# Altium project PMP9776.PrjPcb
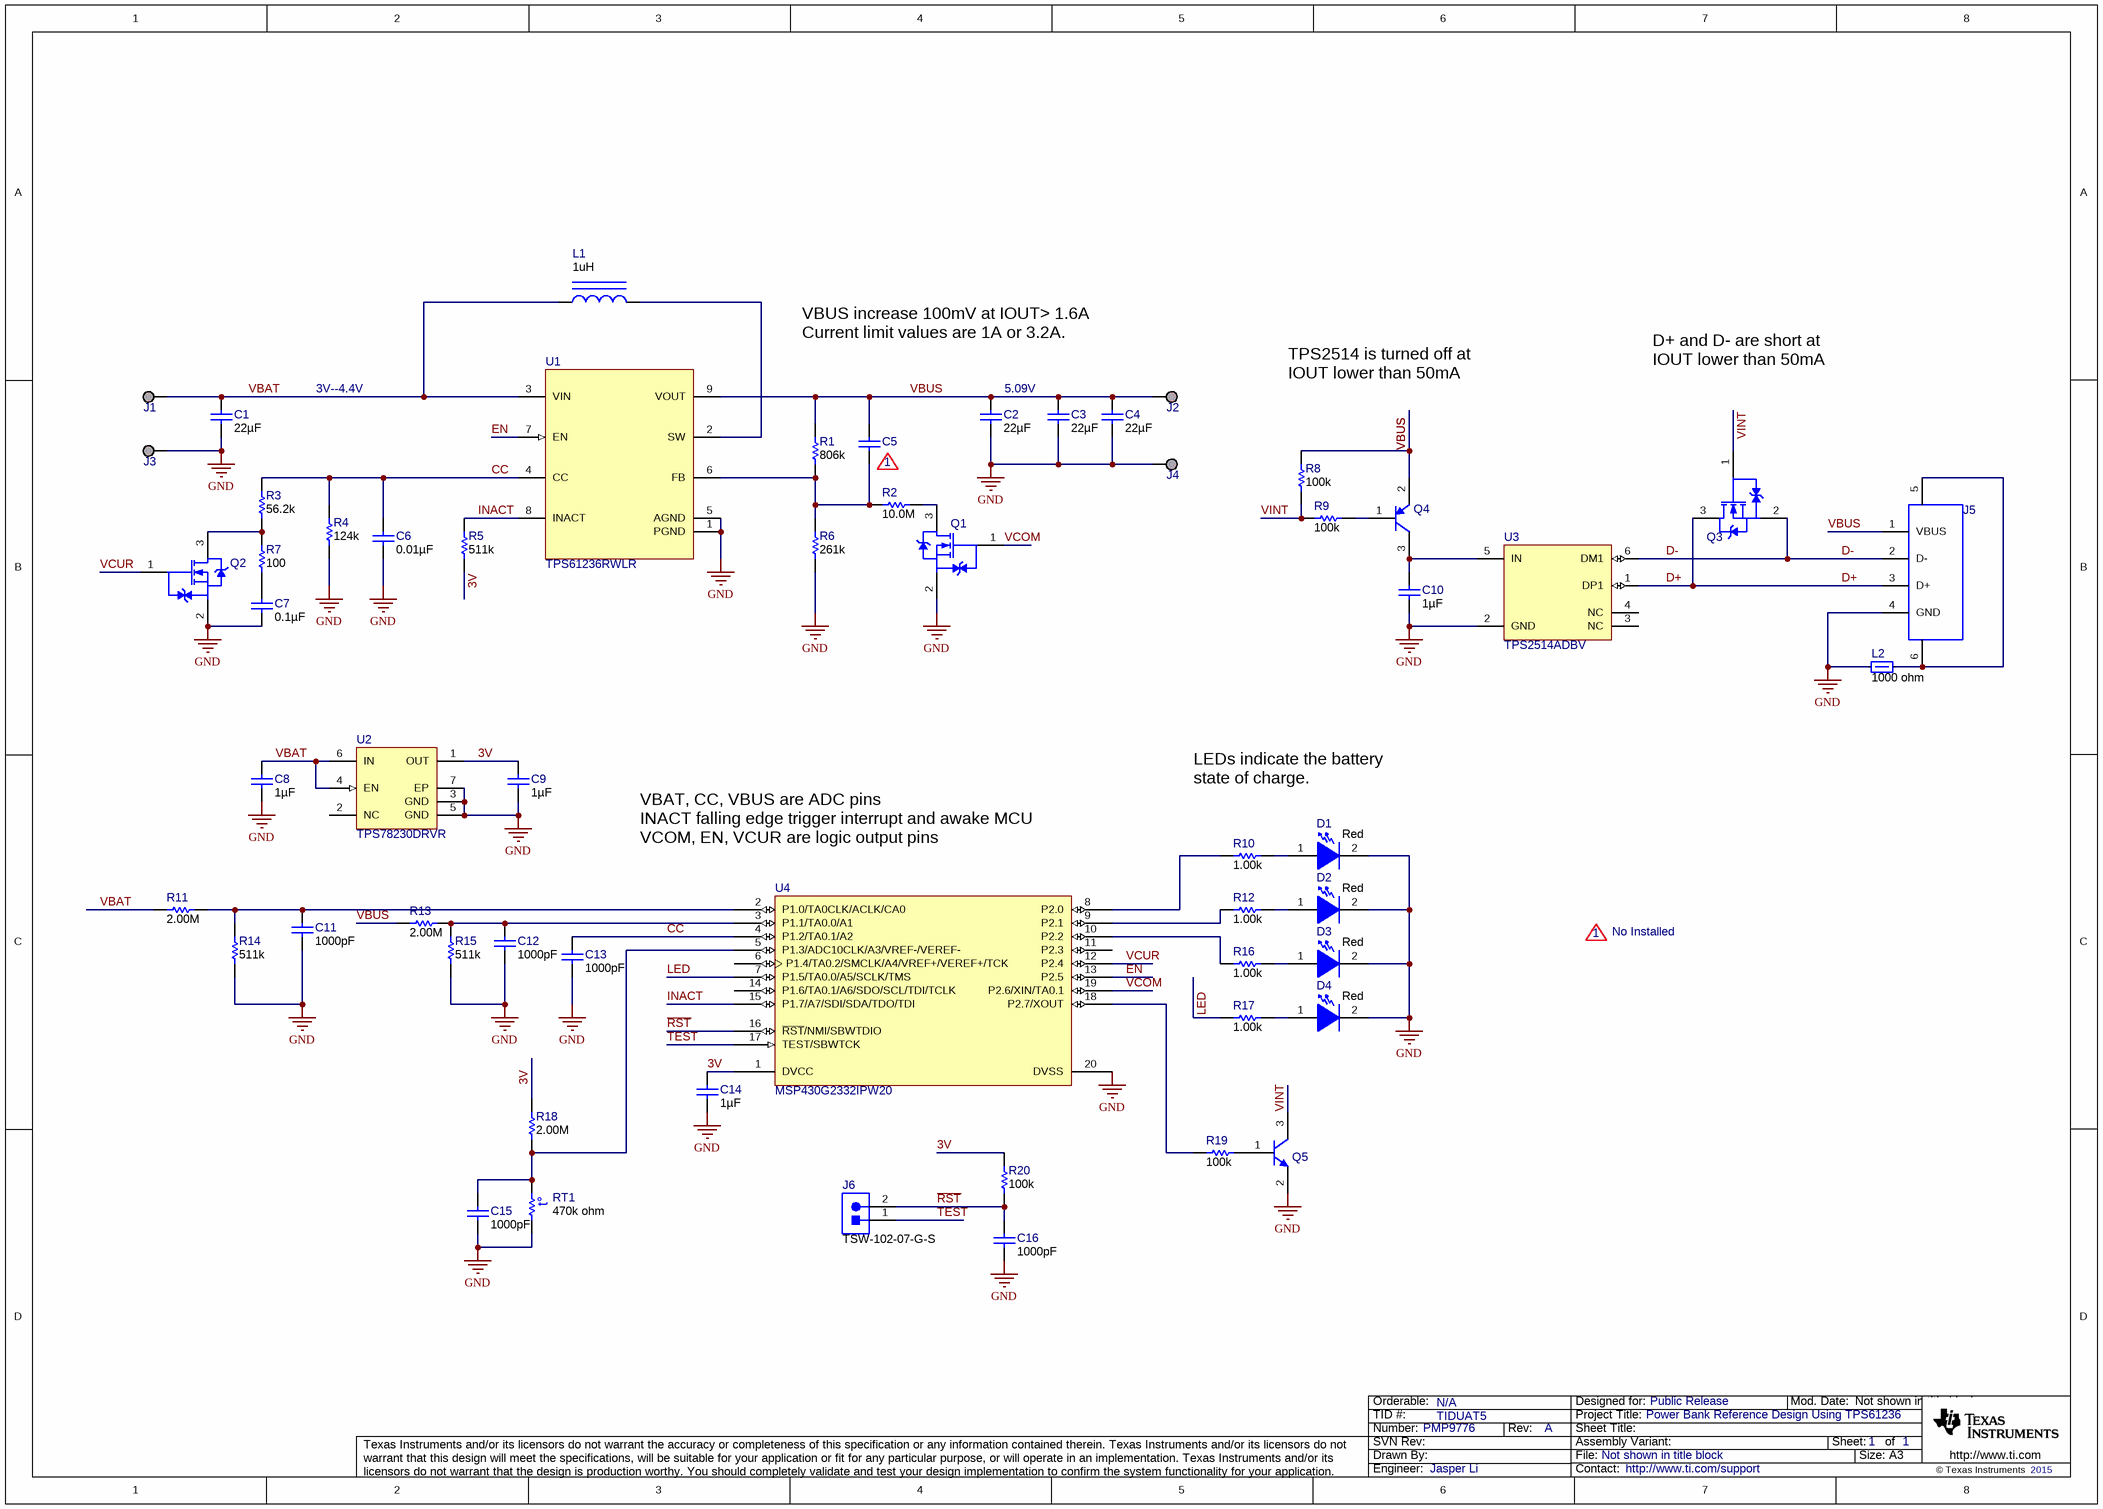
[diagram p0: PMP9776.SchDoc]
TID: TIDUAT5; TechSupport: http://www.ti.com/support; SCH_Rev: A; PRJ_Title: Power Bank Reference Design Using TPS61236; PRJ_Number: PMP9776; PRJ_Engineer: Jasper Li; PRJ_Customer: Public Release; PCB_Rev: A; PCB_Layout: Jasper Li; EVM_Orderable: N/A; CopyrightYear: 2015
2 sheets, 60 parts. Net scope: global (net labels, ports and power ports of the same name join across sheets).
Board file: PMP9776.PcbDoc
Sheets:
  PMP9776.SchDoc
  PMP9776_Hardware.SchDoc

## Sheet PMP9776.SchDoc
size A3; Date: Not shown in title block; ApprovedBy: Not shown in title block; CheckedBy: Not shown in title block; Author: Not shown in title block; CompanyName: Not shown in title block; Engineer: Not shown in title block; Organization: Not shown in title block; Address1: Not shown in title block; Address2: Not shown in title block; Address3: Not shown in title block; Address4: Not shown in title block; DocumentNumber: 1; Revision: Use project parameter SCH_Rev; SheetNumber: 1; SheetTotal: 1; PageSetup: Record=PageOptions¦CenterHorizontal=True¦CenterVertical=True¦PrintScale=0.70¦XCorrection=1.00¦YCorrection=1.00¦PrintKind=0¦BorderSize=5000000¦LeftOffset=0¦BottomOffset=0¦Orientation=2¦PaperLength=1000¦PaperWidth=1000¦Scale=100¦PaperSource=15¦PrintQuality=600¦MediaType=1¦DitherType=10¦PrintScaleMode=1¦PaperKind=Letter

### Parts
C1  ValueDisplayed: 22µF  [0805L]  (hidden comment: GRM21BR61A226ME44)
C2  ValueDisplayed: 22µF  [0805L]  (hidden comment: GRM21BR61A226ME44)
C3  ValueDisplayed: 22µF  [0805L]  (hidden comment: GRM21BR61A226ME44)
C4  ValueDisplayed: 22µF  [0805L]  (hidden comment: GRM21BR61A226ME44)
C5  GRM1555C1H100JA01D  [0402L]  (value not drawn)
C6  ValueDisplayed: 0.01µF  [0402L]  (hidden comment: GRM155R71H103KA88D)
C7  ValueDisplayed: 0.1µF  [0402L]  (hidden comment: GRM155R71E104KE14D)
C8  ValueDisplayed: 1µF  [0402L]  (hidden comment: GRM155R61A105KE15D)
C9  ValueDisplayed: 1µF  [0402L]  (hidden comment: GRM155R61A105KE15D)
C10  ValueDisplayed: 1µF  [0402L]  (hidden comment: GRM155R61A105KE15D)
C11  ValueDisplayed: 1000pF  [0402L]  (hidden comment: GRM155R71H102KA01D)
C12  ValueDisplayed: 1000pF  [0402L]  (hidden comment: GRM155R71H102KA01D)
C13  ValueDisplayed: 1000pF  [0402L]  (hidden comment: GRM155R71H102KA01D)
C14  ValueDisplayed: 1µF  [0402L]  (hidden comment: GRM155R61A105KE15D)
C15  ValueDisplayed: 1000pF  [0402L]  (hidden comment: GRM155R71H102KA01D)
C16  ValueDisplayed: 1000pF  [0402L]  (hidden comment: GRM155R71H102KA01D)
D1  value Red  [HSMx-C190_Red]  (hidden comment: HSMC-C190)
D2  value Red  [HSMx-C190_Red]  (hidden comment: HSMC-C190)
D3  value Red  [HSMx-C190_Red]  (hidden comment: HSMC-C190)
D4  value Red  [HSMx-C190_Red]  (hidden comment: HSMC-C190)
J1  Suggest using a net name here  [Keystone1502-2]  (value not drawn)
J2  Suggest using a net name here  [Keystone1502-2]  (value not drawn)
J3  Suggest using a net name here  [Keystone1502-2]  (value not drawn)
J4  Suggest using a net name here  [Keystone1502-2]  (value not drawn)
J5  614 104 150 121  [WURTH_614104150121]  (value not drawn)
J6  TSW-102-07-G-S  [TSW-102-07-G-S]
L1  value 1uH  [FDSD0630]  (hidden comment: FDSD0630-H-1R0M)
L2  value 1000 ohm  [WE-CBF_0603]  (hidden comment: 74279266A)
Q1  SI1012CR-T1-GE3-ND  [SOT-416]  (value not drawn)
Q2  SI1012CR-T1-GE3-ND  [SOT-416]  (value not drawn)
Q3  SI1012CR-T1-GE3-ND  [SOT-416]  (value not drawn)
Q4  MMBT3906  [SOT-23]  (value not drawn)
Q5  MMBT3904  [SOT-23]  (value not drawn)
R1  ValueDisplayed: 806k  [0402L]  (hidden comment: CRCW0402806KFKED)
R2  ValueDisplayed: 10.0M  [0402L]  (hidden comment: CRCW040210M0FKED)
R3  ValueDisplayed: 56.2k  [0402L]  (hidden comment: CRCW040256K2FKED)
R4  ValueDisplayed: 124k  [0402L]  (hidden comment: CRCW0402124KFKED)
R5  ValueDisplayed: 511k  [0402L]  (hidden comment: CRCW0402511KFKED)
R6  ValueDisplayed: 261k  [0402L]  (hidden comment: CRCW0402261KFKED)
R7  ValueDisplayed: 100  [0402L]  (hidden comment: CRCW0402100RFKED)
R8  ValueDisplayed: 100k  [0402L]  (hidden comment: CRCW0402100KFKED)
R9  ValueDisplayed: 100k  [0402L]  (hidden comment: CRCW0402100KFKED)
R10  ValueDisplayed: 1.00k  [0402L]  (hidden comment: CRCW04021K00FKED)
R11  ValueDisplayed: 2.00M  [0402L]  (hidden comment: CRCW04022M00FKED)
R12  ValueDisplayed: 1.00k  [0402L]  (hidden comment: CRCW04021K00FKED)
R13  ValueDisplayed: 2.00M  [0402L]  (hidden comment: CRCW04022M00FKED)
R14  ValueDisplayed: 511k  [0402L]  (hidden comment: CRCW0402511KFKED)
R15  ValueDisplayed: 511k  [0402L]  (hidden comment: CRCW0402511KFKED)
R16  ValueDisplayed: 1.00k  [0402L]  (hidden comment: CRCW04021K00FKED)
R17  ValueDisplayed: 1.00k  [0402L]  (hidden comment: CRCW04021K00FKED)
R18  ValueDisplayed: 2.00M  [0402L]  (hidden comment: CRCW04022M00FKED)
R19  ValueDisplayed: 100k  [0402L]  (hidden comment: CRCW0402100KFKED)
R20  ValueDisplayed: 100k  [0402L]  (hidden comment: CRCW0402100KFKED)
RT1  value 470k ohm  [0402L]  (hidden comment: NCP15WM474J03RC)
U1  TPS61236RWLR  [RWL0009A]
U2  TPS78230DRVR  [DRV0006A]
U3  TPS2514ADBV  [DBV0006A_N]
U4  MSP430G2332IPW20  [PW0020A_N]

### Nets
GND: C1.2 C2.2 C3.2 C4.2 C6.2 C7.2 C8.2 C9.2 C10.2 C11.1 C12.1 C13.1 C14.2 C15.1 C16.1 D1.2(K) D2.2(K) D3.2(K) D4.2(K) J3.1 J4.1 J5.4(GND) L2.1 Q1.2(S) Q2.2(S) Q5.2(E) R4.1 R6.1 R14.1 R15.1 RT1.1 U1.1(PGND) U1.5(AGND) U2.3(GND) U2.5(GND) U2.7(EP) U3.2(GND) U4.20(DVSS)
3V: C9.1 C14.1 R5.1 R18.2 R20.2 U2.1(OUT) U4.1(DVCC)
CC: C6.1 C13.2 R3.2 R4.2 U1.4(CC) U4.4(P1.2/TA0.1/A2)
D+: J5.3(D+) Q3.3(D) U3.1(DP1)
D-: J5.2(D-) Q3.2(S) U3.6(DM1)
EN: U1.7(EN) U4.13(P2.5)
INACT: R5.2 U1.8(INACT) U4.15(P1.7/A7/SDI/SDA/TDO/TDI)
LED: R17.1 U4.7(P1.5/TA0.0/A5/SCLK/TMS)
~{RST}: C16.2 J6.2 R20.1 U4.16(~{RST}/NMI/SBWTDIO)
TEST: J6.1 U4.17(TEST/SBWTCK)
VBAT: C1.1 C8.1 J1.1 L1.1 R11.1 U1.3(VIN) U2.4(EN) U2.6(IN)
VBUS: C2.1 C3.1 C4.1 C5.1 J2.1 J5.1(VBUS) Q4.2(E) R1.2 R8.2 R13.1 U1.9(VOUT)
VCOM: Q1.1(G) U4.19(P2.6/XIN/TA0.1)
VCUR: Q2.1(G) U4.12(P2.4)
VINT: Q3.1(G) Q5.3(C) R8.1 R9.2
NetC5_2: C5.2 R1.1 R2.2 R6.2 U1.6(FB)
NetC7_1: C7.1 R7.1
NetC10_1: C10.1 Q4.3(C) U3.5(IN)
NetC11_2: C11.2 R11.2 R14.2 U4.2(P1.0/TA0CLK/ACLK/CA0)
NetC12_2: C12.2 R13.2 R15.2 U4.3(P1.1/TA0.0/A1)
NetC15_2: C15.2 R18.1 RT1.2 U4.5(P1.3/ADC10CLK/A3/VREF-/VEREF-)
NetD1_1: D1.1(A) R10.2
NetD2_1: D2.1(A) R12.2
NetD3_1: D3.1(A) R16.2
NetD4_1: D4.1(A) R17.2
NetJ5_5: J5.5(Shield) J5.6(Shield) L2.2
NetL1_2: L1.2 U1.2(SW)
NetQ1_3: Q1.3(D) R2.1
NetQ2_3: Q2.3(D) R3.1 R7.2
NetQ4_1: Q4.1(B) R9.1
NetQ5_1: Q5.1(B) R19.1
NetR10_1: R10.1 U4.8(P2.0)
NetR12_1: R12.1 U4.9(P2.1)
NetR16_1: R16.1 U4.10(P2.2)
NetR19_2: R19.2 U4.18(P2.7/XOUT)

Not connected (* = marked no-connect by the designer): U2 2(NC); U3 3(NC) 4(NC); U4 6(P1.4/TA0.2/SMCLK/A4/VREF+/VEREF+/TCK) 11(P2.3) 14(P1.6/TA0.1/A6/SDO/SCL/TDI/TCLK)

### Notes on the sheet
- VBUS increase 100mV at IOUT> 1.6A
  Current limit values are 1A or 3.2A.
- TPS2514 is turned off at IOUT lower than 50mA
- D+ and D- are short at IOUT lower than 50mA
- 3V--4.4V
- 5.09V
- (near C5) 1
- LEDs indicate the battery state of charge.
- VBAT, CC, VBUS are ADC pins
  INACT falling edge trigger interrupt and awake MCU
  VCOM, EN, VCUR are logic output pins
- 1
- No Installed

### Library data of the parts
C1-C4 = GRM21BR61A226ME44: CAP, CERM, 22uF, 10V, +/-20%, X5R, 0805; Manufacturer: MuRata; Polarized: N; CompType: Capacitor; U/M: EA; Cap_F: 0.000022; Tolerance_%: 20; Value1: Unknown; VDC_V: 10; TaMin_C: -55; TaMax_C: 85; Cap_Case: 0805
C5 = GRM1555C1H100JA01D: CAP, CERM, 10 pF, 50 V, +/- 5%, C0G/NP0, 0402; Manufacturer: MuRata; Polarized: N; CompType: Capacitor; Value: 10pF; U/M: EA; Cap_F: 0.00000000001; Tolerance_%: 5; Value1: Unknown; VDC_V: 50; Value2: 50V; TaMin_C: -55; TaMax_C: 125; Cap_Case: 0402
C6 = GRM155R71H103KA88D: CAP, CERM, 0.01 µF, 50 V, +/- 10%, X7R, 0402; Manufacturer: MuRata; Polarized: N; CompType: Capacitor; Value: 0.01uF; U/M: EA; Cap_F: 0.00000001; Tolerance_%: 10; Value1: Unknown; VDC_V: 50; Value2: 50V; TaMin_C: -55; TaMax_C: 125; Cap_Case: 0402
C7 = GRM155R71E104KE14D: CAP, CERM, 0.1 µF, 25 V, +/- 10%, X7R, 0402; Manufacturer: MuRata; Polarized: N; CompType: Capacitor; Value: 0.1uF; U/M: EA; Cap_F: 0.0000001; Tolerance_%: 10; Value1: Unknown; VDC_V: 25; Value2: 25V; TaMin_C: -55; TaMax_C: 125; Cap_Case: 0402; AEC Category: Q200
C8-C10 C14 = GRM155R61A105KE15D: CAP, CERM, 1 µF, 10 V, +/- 10%, X5R, 0402; Manufacturer: MuRata; Polarized: N; CompType: Capacitor; Value: 1uF; U/M: EA; Cap_F: 0.000001; Tolerance_%: 10; Value1: Unknown; Value2: 10V; TaMin_C: -55; TaMax_C: 85; Cap_Case: 0402
C11-C13 C15 C16 = GRM155R71H102KA01D: CAP, CERM, 1000 pF, 50 V, +/- 10%, X7R, 0402; Manufacturer: MuRata; Polarized: N; CompType: Capacitor; Value: 1000pF; U/M: EA; Cap_F: 0.000000001; Tolerance_%: 10; Value1: Unknown; VDC_V: 50; Value2: 50V; TaMin_C: -55; TaMax_C: 125; Cap_Case: 0402
D1-D4 = HSMC-C190: LED, Red, SMD; Manufacturer: Avago; Type: AlInGaP; Vf_V: 1.9; Value2: 1.9V; Io_A: 0.02; Vr_V: 5; Ir_A: 0.0001; Tjmax_C: 95; Power_TotalModule: 0.06; Value1: 0.06W; Angle: 170; U/M: EA
J1-J4 = 1502-2: Terminal, Turret, TH, Double; Manufacturer: Keystone; CompType: Turret Terminal; U/M: EA
J5 = 614 104 150 121: Connector, Receptacle, USB Type A, R/A, Bottom Mount TH; Manufacturer: Wurth Elektronik; SymbolCreator: a0412235; U/M: EA
J6 = TSW-102-07-G-S: Header, 100mil, 2x1, Gold, TH; Manufacturer: Samtec; SymbolCreator: a0412235; U/M: EA
L1 = FDSD0630-H-1R0M: Inductor, Shielded, Metal Composite, 1 µH, 9.4 A, 0.009 ohm, SMD; Manufacturer: Toko; Ind_H: 1.0E-6; ValueDisplayed: 1µH; Imax_A: 9.4; Irms: 9.4A @ 40C rise; Isat: 15A @ 30% inductance drop; DCR_ohm: 0.009; Value2: 9.4A
L2 = 74279266A: Ferrite Bead, 1000 ohm @ 100 MHz, 0.2 A, 0603; Manufacturer: Wurth Elektronik; Imax_A: 0.2; DCR_ohm: 0.6; Value1: 0.6 ohm; Value2: 0.2A; ZTyp@100MHz_Ohm: 1000
Q1-Q3 = SI1012CR-T1-GE3-ND: MOSFET, N/P-CH, 20 V, 0.63 A, SOT-416; Manufacturer: Vishay-Siliconix; Alternate Manufacturer: None; SymbolCreator: a0411947; U/M: EA; ChType: N; Value: 20V; VdsMax_V: 20; Value1: 0.396 ohm; Rdson45_ohm: 0.396; Value2: 2 nC; QgTyp_nC: 2; Vgs_V: 8; IdsMax_A: 0.63
Q4 = MMBT3906, Fairchild Semiconductor: Transistor, PNP, 40 V, 0.2 A, SOT-23; CompType: BJT; PNP: 1; NPN: 0; Vceo_V: 40; Vcesat1_V: 0.25; Value: 40 V; IcRated_A: 0.2; Value1: 0.2 A; HfeMax: 300; TaMin_C: -55; TaMax_C: 150; U/M: EA
Q5 = MMBT3904, Fairchild Semiconductor: Transistor, NPN, 40 V, 0.2 A, SOT-23; CompType: BJT; PNP: 0; NPN: 1; Vceo_V: 40; Vcesat1_V: 0.2; Value: 40 V; Value1: 0.2 A; HfeMax: 300; TaMin_C: -55; TaMax_C: 150; U/M: EA
R1 = CRCW0402806KFKED: RES, 806 k, 1%, 0.063 W, 0402; Manufacturer: Vishay-Dale; CompType: Resistor; Value: 806k; Res_ohm: 806000; Tolerance_%: 1; Power_W: 0.063; Value2: 0.063W; VDC_V: 50; TempCo: 100 ppm/C; EIA_Code: E96; U/M: EA
R2 = CRCW040210M0FKED: RES, 10.0 M, 1%, 0.063 W, 0402; Manufacturer: Vishay-Dale; CompType: Resistor; Value: 10.0Meg; Res_ohm: 10000000; Value_Code: 10M0; Tolerance_%: 1; Power_W: 0.063; Value2: 0.063W; VDC_V: 50; TempCo: 100 ppm/C; EIA_Code: E96; U/M: EA
R3 = CRCW040256K2FKED: RES, 56.2 k, 1%, 0.063 W, 0402; Manufacturer: Vishay-Dale; CompType: Resistor; Value: 56.2k; Res_ohm: 56200; Value_Code: 56k2; Tolerance_%: 1; Power_W: 0.063; Value2: 0.063W; VDC_V: 50; TempCo: 100 ppm/C; EIA_Code: E96; U/M: EA
R4 = CRCW0402124KFKED: RES, 124 k, 1%, 0.063 W, 0402; Manufacturer: Vishay-Dale; CompType: Resistor; Value: 124k; Res_ohm: 124000; Tolerance_%: 1; Power_W: 0.063; Value2: 0.063W; VDC_V: 50; TempCo: 100 ppm/C; EIA_Code: E96; U/M: EA
R5 R14 R15 = CRCW0402511KFKED: RES, 511 k, 1%, 0.063 W, 0402; Manufacturer: Vishay-Dale; CompType: Resistor; Value: 511k; Res_ohm: 511000; Tolerance_%: 1; Power_W: 0.063; Value2: 0.063W; VDC_V: 50; TempCo: 100 ppm/C; EIA_Code: E96; U/M: EA
R6 = CRCW0402261KFKED: RES, 261 k, 1%, 0.063 W, 0402; Manufacturer: Vishay-Dale; CompType: Resistor; Value: 261k; Res_ohm: 261000; Tolerance_%: 1; Power_W: 0.063; Value2: 0.063W; VDC_V: 50; TempCo: 100 ppm/C; EIA_Code: E96; U/M: EA
R7 = CRCW0402100RFKED: RES, 100, 1%, 0.063 W, 0402; Manufacturer: Vishay-Dale; CompType: Resistor; Value: 100; Value_Code: 100R; Tolerance_%: 1; Power_W: 0.063; Value2: 0.063W; VDC_V: 50; TempCo: 100 ppm/C; EIA_Code: E96; U/M: EA
R8 R9 R19 R20 = CRCW0402100KFKED: RES, 100 k, 1%, 0.063 W, 0402; Manufacturer: Vishay-Dale; CompType: Resistor; Value: 100k; Res_ohm: 100000; Tolerance_%: 1; Power_W: 0.063; Value2: 0.063W; VDC_V: 50; TempCo: 100 ppm/C; EIA_Code: E96; U/M: EA
R10 R12 R16 R17 = CRCW04021K00FKED: RES, 1.00 k, 1%, 0.063 W, 0402; Manufacturer: Vishay-Dale; CompType: Resistor; Value: 1.00k; Res_ohm: 1000; Value_Code: 1k00; Tolerance_%: 1; Power_W: 0.063; Value2: 0.063W; VDC_V: 50; TempCo: 100 ppm/C; EIA_Code: E96; U/M: EA
R11 R13 R18 = CRCW04022M00FKED: RES, 2.00 M, 1%, 0.063 W, 0402; Manufacturer: Vishay-Dale; CompType: Resistor; Value: 2.00Meg; Res_ohm: 2000000; Value_Code: 2M00; Tolerance_%: 1; Power_W: 0.063; Value2: 0.063W; VDC_V: 50; TempCo: 100 ppm/C; EIA_Code: E96; U/M: EA
RT1 = NCP15WM474J03RC: Thermistor NTC, 470k ohm, 5%, 0402; Manufacturer: MuRata; Tolerance_%: 5; Power_W: 0.1; TaMin_C: -40; TaMax_C: 125; U/M: EA
U1 = TPS61236RWLR: 7-A Synchronous Boost Converter with Programmable Output Current Limit, RWL0009A; Alternate PartNumber: TPS61236RWLT; Manufacturer: Texas Instruments; SymbolCreator: a0411947; CompType: IC; U/M: EA
U2 = TPS78230DRVR: Single Output LDO, 150 mA, Fixed 3 V Output, 2.2 to 5.5 V Input, with 0.5 uA Quiescent Current, 6-pin SON (DRV), -40 to 125 degC, Green (RoHS & no Sb/Br); Manufacturer: Texas Instruments; Alternate Manufacturer: None; Alternate PartNumber: Equivalent; Accuracy(%): 3; Dynamic Voltage Scaling: TRUE; Iout(Max)(A): 0.15; Iq(Typ)(mA): 0.0005; Rating: Catalog; SubFamily: Single Channel LDO; Vdo(Typ)(mV): 130; Vin(Max)(V): 5.5; Vin(Min)(V): 2.2
U3 = TPS2514ADBV: USB Dedicated Charging Port Controller, DBV0006A; Manufacturer: Texas Instruments; SymbolCreator: a0411947; CompType: IC; U/M: EA
U4 = MSP430G2332IPW20: 16 MHz Mixed Signal Microcontroller with 4 KB Flash, 256 B SRAM and 16 GPIOs, 20-pin SOP (PW), Green (RoHS & no Sb/Br); Alternate Manufacturer: Texas Instruments; Alternate PartNumber: Equivalent; ADC: 10-bit SAR; ADC Channels: 8; Brown Out Reset: Yes; Flash(KB): 4; Frequency(MHz): 16; Pin/Package: 14TSSOP, 16QFN, 20PDIP, 20TSSOP; SRAM(B): 256; SubFamily: Value Line; Timers - 16-bit: 1; USI: (I2C/SPI)

## Sheet PMP9776_Hardware.SchDoc
size A4; Date: Not shown in title block; ApprovedBy: Not shown in title block; CheckedBy: Not shown in title block; Author: Not shown in title block; CompanyName: Not shown in title block; Engineer: Not shown in title block; Organization: Not shown in title block; Address1: Not shown in title block; Address2: Not shown in title block; Address3: Not shown in title block; Address4: Not shown in title block; DocumentNumber: 1; Revision: Use project parameter SCH_Rev; SheetNumber: 1; SheetTotal: 1; PageSetup: Record=PageOptions¦CenterHorizontal=True¦CenterVertical=True¦PrintScale=1.00¦XCorrection=1.00¦YCorrection=1.00¦PrintKind=0¦BorderSize=5000000¦LeftOffset=0¦BottomOffset=0¦Orientation=2¦PaperLength=1000¦PaperWidth=1000¦Scale=100¦PaperSource=15¦PrintQuality=600¦MediaType=1¦DitherType=10¦PaperKind=Letter¦PrintScaleMode=1
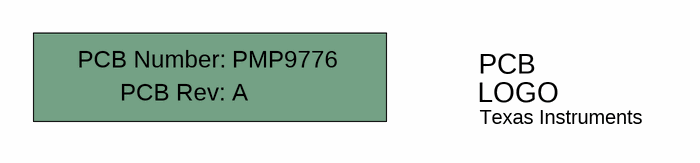
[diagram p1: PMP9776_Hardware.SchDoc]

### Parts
!PCB1  Printed Circuit Board  (value not drawn)  (mechanical)
Logo1  Texas Instruments  [TI_Stacked_Overlay_Small]  (no BOM)

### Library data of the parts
!PCB1 = PCB: Manufacturer: Any; PartNumber: PMP9776; SymbolCreator: a0412235
Logo1 = TI_Logo: Texas Instrument Corporate Signature; SymbolCreator: a0412235

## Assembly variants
001: not fitted FID1 FID2 FID3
